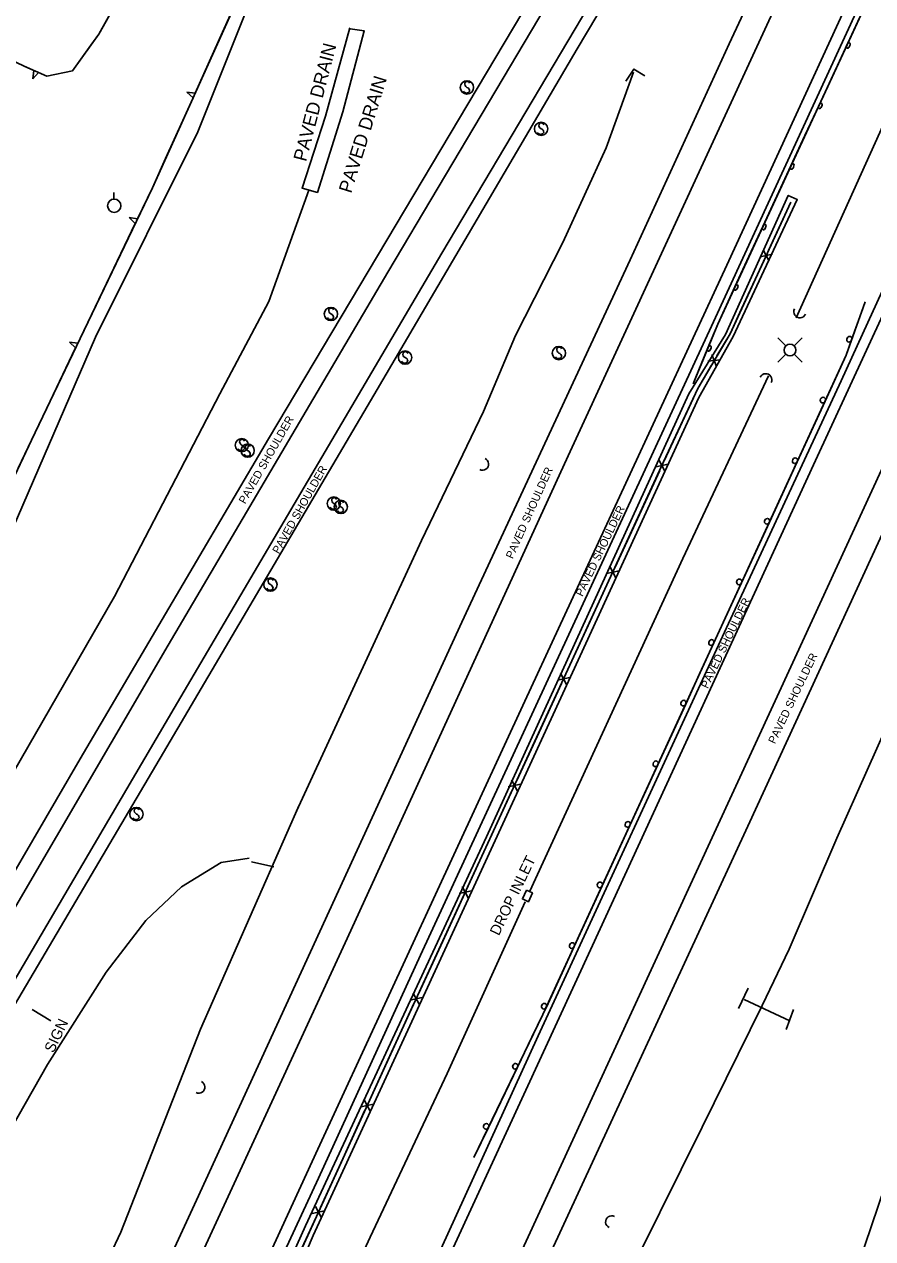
# Model space of a CAD drawing. Extents: x 978516 to 993312, y 1836504 to 1846212.
# Drawn here: x 981689.2 to 982007, y 1842943.3 to 1843398.4 of the extents above; entities that cross this region are included whole.
import ezdxf

# ---------------------------------------------------------------- set-up
doc = ezdxf.new("R2010")
doc.units = 0
for name, color, linetype in [('S_CROSS_DRAIN', 7, 'Continuous'), ('S_DROP_INLET', 7, 'Continuous'), ('S_DROP_INLET_ANNOT', 7, 'Continuous'), ('S_EDGE_PAVEMENT', 7, 'Continuous'), ('S_FENCE', 7, 'Continuous'), ('S_GUARDRAIL', 7, 'Continuous'), ('S_HEADWALL', 7, 'Continuous'), ('S_MISC_STRUCTURES', 7, 'Continuous'), ('S_SHOULDER', 7, 'Continuous'), ('S_SHOULDER_ANNOT', 7, 'Continuous'), ('S_SIDE_DRAIN', 7, 'Continuous'), ('S_SIDE_DRAIN_ANNOT', 7, 'Continuous'), ('S_SIGN', 7, 'Continuous'), ('S_SIGN_ANNOT', 7, 'Continuous'), ('S_STREAM', 7, 'Continuous'), ('S_TRAILS', 7, 'Continuous'), ('S_TREE', 7, 'Continuous'), ('S_UTILITY_POLE', 7, 'Continuous')]:
    doc.layers.add(name, color=color, linetype=linetype)

msp = doc.modelspace()

# ---------------------------------------------------------------- linework, layer by layer
at = {"layer": 'S_CROSS_DRAIN'}
for centre, start, end in [((981979.7, 1843290.68), 153.9932, 334.3223), ((981966.89, 1843265.14), 333.0286, 153.3578), ((981860.81, 1843233.55), 243.9932, 64.3223), ((981754.54, 1843000.07), 243.9932, 64.3223), ((981909.24, 1842949.54), 63.9932, 244.3223)]:
    msp.add_arc(centre, 2.3, start, end, dxfattribs=at)
at = {"layer": 'S_DROP_INLET'}
msp.add_lwpolyline([(981877.3, 1843073.82), (981875.77, 1843070.61), (981877.99, 1843069.55), (981879.53, 1843072.82), (981877.24, 1843073.92)], dxfattribs=at)
at = {"layer": 'S_EDGE_PAVEMENT'}
for points in [[(981545.48, 1842840.54), (981594.83, 1842916.9), (981606.14, 1842933.63), (981624.73, 1842964.36), (981679.78, 1843057.43), (981743.14, 1843165.74), (981825.37, 1843305.52), (981900.71, 1843432.47), (981943.19, 1843504.28), (981976.52, 1843560.47)], [(981988.52, 1843553.82), (981924.19, 1843445.19), (981845.55, 1843312.63), (981745.28, 1843142.12), (981686.64, 1843042.02), (981635.51, 1842955.23), (981602.62, 1842899.17)], [(982046.43, 1843512.73), (982020.19, 1843455.64), (981952.29, 1843308.15), (981876.66, 1843144.67), (981799.12, 1842976.8), (981735.97, 1842839.3)], [(981789.25, 1842808.86), (981838.12, 1842914.35), (981901.96, 1843053.16), (981984.85, 1843233.32), (982064.19, 1843405.17), (982101.67, 1843487.19)], [(981691.52, 1842798.76), (981749.14, 1842923.61), (981810.07, 1843055.75), (981892.92, 1843236.68), (981965.86, 1843394.8), (982005.62, 1843481.17)], [(982119.03, 1843466.37), (982096.74, 1843418.67), (982029, 1843272.11), (981977.78, 1843160.81), (981902.68, 1842997.65), (981844.43, 1842871.29), (981807.01, 1842789.3)]]:
    msp.add_lwpolyline(points, dxfattribs=at)
at = {"layer": 'S_FENCE'}
for p, q in [((981969.44, 1843312.23), (981964.79, 1843311.25)), ((981966, 1843313.85), (981968.24, 1843309.62)), ((981949.97, 1843272.59), (981945.26, 1843272.12)), ((981946.72, 1843274.59), (981948.52, 1843270.13)), ((981926.92, 1843235.12), (981929.17, 1843230.9)), ((981930.37, 1843233.51), (981925.72, 1843232.52)), ((981911.95, 1843193.55), (981907.3, 1843192.56)), ((981908.5, 1843195.17), (981910.75, 1843190.95)), ((981893.53, 1843153.59), (981888.88, 1843152.6)), ((981890.08, 1843155.21), (981892.33, 1843150.99)), ((981875.11, 1843113.63), (981870.46, 1843112.64)), ((981871.66, 1843115.25), (981873.91, 1843111.03)), ((981853.24, 1843075.29), (981855.49, 1843071.07)), ((981856.69, 1843073.67), (981852.04, 1843072.68)), ((981838.28, 1843033.71), (981833.63, 1843032.72)), ((981834.83, 1843035.33), (981837.08, 1843031.11)), ((981819.95, 1842993.72), (981815.3, 1842992.71)), ((981816.49, 1842995.32), (981818.76, 1842991.11)), ((981801.67, 1842953.7), (981797.02, 1842952.68)), ((981798.21, 1842955.29), (981800.48, 1842951.09))]:
    msp.add_line(p, q, dxfattribs=at)
for points in [[(981976.36, 1843331.7), (981953.53, 1843282.4), (981941.43, 1843261.84), (981928.66, 1843234.35), (981829.82, 1843019.91), (981787.4, 1842927.02), (981725.99, 1842788.22)], [(981976.36, 1843331.7), (981967.96, 1843313.55)], [(981966.28, 1843309.92), (981957.87, 1843291.78)], [(981957.87, 1843291.78), (981953.53, 1843282.4), (981948.63, 1843274.08)], [(981946.6, 1843270.63), (981941.43, 1843261.84), (981937.3, 1843252.97)], [(981937.3, 1843252.97), (981928.88, 1843234.83)], [(981927.2, 1843231.2), (981918.83, 1843213.03)], [(981918.83, 1843213.03), (981910.46, 1843194.87)], [(981908.79, 1843191.24), (981900.41, 1843173.08)], [(981900.41, 1843173.08), (981892.04, 1843154.91)], [(981890.37, 1843151.28), (981882, 1843133.12)], [(981882, 1843133.12), (981873.62, 1843114.95)], [(981871.95, 1843111.32), (981863.58, 1843093.16)], [(981863.58, 1843093.16), (981855.21, 1843074.99)], [(981853.53, 1843071.36), (981845.16, 1843053.2)], [(981845.16, 1843053.2), (981836.79, 1843035.04)], [(981835.11, 1843031.4), (981829.82, 1843019.91), (981826.77, 1843013.23)], [(981826.77, 1843013.23), (981818.46, 1842995.04)], [(981816.8, 1842991.4), (981808.49, 1842973.2)], [(981808.49, 1842973.2), (981800.18, 1842955.01)], [(981798.52, 1842951.37), (981790.21, 1842933.18)]]:
    msp.add_lwpolyline(points, dxfattribs=at)
at = {"layer": 'S_GUARDRAIL'}
for points in [[(982087.36, 1843583.1), (982082.81, 1843573.61), (982024.65, 1843449.71), (981948.94, 1843286.05), (981939.76, 1843263.65)], [(982002.6, 1843402.05), (981997.35, 1843390.7)], [(981997.35, 1843390.7), (981986.86, 1843368.01)], [(981986.86, 1843368.01), (981981.61, 1843356.67)], [(981981.61, 1843356.67), (981976.36, 1843345.33)], [(981976.36, 1843345.33), (981965.86, 1843322.64)], [(981965.86, 1843322.64), (981960.62, 1843311.29)], [(981960.62, 1843311.29), (981955.37, 1843299.95)], [(981955.37, 1843299.95), (981948.94, 1843286.05), (981945.27, 1843277.09)], [(981857.6, 1842973.72), (981883.47, 1843027.27), (981997.07, 1843274.39), (982004.19, 1843294.39)], [(982003.27, 1843291.81), (982004.19, 1843294.39)], [(981999.09, 1843280.06), (982003.27, 1843291.81)], [(981989.15, 1843257.16), (981997.07, 1843274.39), (981999.09, 1843280.06)], [(981945.27, 1843277.09), (981940.53, 1843265.52)], [(981940.53, 1843265.52), (981939.76, 1843263.65)], [(981983.93, 1843245.8), (981989.15, 1843257.16)], [(981978.71, 1843234.45), (981983.93, 1843245.8)], [(981968.27, 1843211.73), (981978.71, 1843234.45)], [(981963.05, 1843200.38), (981968.27, 1843211.73)], [(981957.82, 1843189.02), (981963.05, 1843200.38)], [(981947.38, 1843166.31), (981957.82, 1843189.02)], [(981942.16, 1843154.95), (981947.38, 1843166.31)], [(981936.94, 1843143.59), (981942.16, 1843154.95)], [(981926.5, 1843120.88), (981936.94, 1843143.59)], [(981921.28, 1843109.52), (981926.5, 1843120.88)], [(981916.06, 1843098.16), (981921.28, 1843109.52)], [(981905.62, 1843075.45), (981916.06, 1843098.16)], [(981900.39, 1843064.09), (981905.62, 1843075.45)], [(981895.17, 1843052.73), (981900.39, 1843064.09)], [(981884.73, 1843030.02), (981895.17, 1843052.73)], [(981879.35, 1843018.74), (981883.47, 1843027.27), (981884.73, 1843030.02)], [(981873.91, 1843007.49), (981879.35, 1843018.74)], [(981863.04, 1842984.98), (981873.91, 1843007.49)], [(981857.6, 1842973.72), (981863.04, 1842984.98)]]:
    msp.add_lwpolyline(points, dxfattribs=at)
for centre, major_axis, ratio in [((981997.84, 1843390.45), (0.45, 1), 0.498865), ((981987.35, 1843367.77), (0.45, 1), 0.498865), ((981976.85, 1843345.08), (0.45, 1), 0.498865), ((981966.35, 1843322.39), (0.45, 1), 0.498865), ((981955.86, 1843299.7), (0.45, 1), 0.498865), ((981998.2, 1843280.33), (-0.488, -0.986), 0.845733), ((981945.78, 1843276.9), (0.43, 1.01), 0.499215), ((981988.3, 1843257.54), (-0.485, -0.987), 0.845763), ((981977.86, 1843234.83), (-0.485, -0.987), 0.845763), ((981967.42, 1843212.11), (-0.485, -0.987), 0.845763), ((981956.97, 1843189.4), (-0.485, -0.987), 0.845763), ((981946.53, 1843166.69), (-0.485, -0.987), 0.845763), ((981936.09, 1843143.97), (-0.485, -0.987), 0.845763), ((981925.65, 1843121.26), (-0.485, -0.987), 0.845763), ((981915.21, 1843098.54), (-0.485, -0.987), 0.845763), ((981904.77, 1843075.83), (-0.485, -0.987), 0.845763), ((981894.32, 1843053.11), (-0.485, -0.987), 0.845763), ((981883.88, 1843030.4), (-0.485, -0.987), 0.845763), ((981873.07, 1843007.88), (-0.503, -0.978), 0.845636), ((981862.19, 1842985.37), (-0.503, -0.978), 0.845636)]:
    msp.add_ellipse(centre, major_axis=major_axis, ratio=ratio, dxfattribs=at)
at = {"layer": 'S_HEADWALL'}
for points in [[(981921.58, 1843378.99), (981917.56, 1843381.56), (981914.55, 1843377.03)], [(981960.3, 1843037.12), (981956.69, 1843029.59)], [(981974.59, 1843021.7), (981977.26, 1843029.14)]]:
    msp.add_lwpolyline(points, dxfattribs=at)
at = {"layer": 'S_MISC_STRUCTURES'}
msp.add_lwpolyline([(981758.16, 1842855.22), (981769.7, 1842879.28), (981797.37, 1842944.5), (981839.44, 1843035.75), (981897.42, 1843161.73), (981941.83, 1843258.45), (981954.76, 1843281.38), (981978.69, 1843332.66), (981975.37, 1843334.26), (981951.81, 1843282.14), (981938.09, 1843259.87), (981862.35, 1843093.85), (981794.52, 1842948.07), (981784.19, 1842924.99), (981766.14, 1842880.54), (981760.86, 1842869.53)], dxfattribs=at)
at = {"layer": 'S_SHOULDER'}
for points in [[(981966.9, 1843557.79), (981899.61, 1843443.02), (981780.61, 1843243.04), (981710.13, 1843123.14), (981639.11, 1843001.22), (981613.46, 1842958.13), (981583.23, 1842910.42)], [(981607.39, 1842897.85), (981658.24, 1842984.78), (981741.32, 1843125.53), (981820.11, 1843259.39), (981896.33, 1843389.2), (981991.91, 1843549.81)], [(981719.94, 1842772.32), (981757.19, 1842850.86), (981762.83, 1842881.77), (981760.47, 1842881.88), (981799.36, 1842965.97), (981837.6, 1843049.54), (981906.21, 1843198.01), (981947.39, 1843286.92), (982066.73, 1843546.13)], [(981999.81, 1843490.91), (981953.15, 1843391.02), (981916.18, 1843310.13), (981853.12, 1843174.31), (981753.64, 1842957.68), (981723.69, 1842892.74), (981694.78, 1842830.18), (981661.51, 1842757.48)], [(982097.08, 1843486.24), (982039.8, 1843362.56), (981995.19, 1843264.75), (981952.2, 1843172.24), (981881.72, 1843019.31), (981832.85, 1842912.29), (981784.9, 1842808.77)], [(982180.73, 1843461.94), (982147.57, 1843365.49), (982120.53, 1843284.55), (982077.03, 1843155.6), (982029.21, 1843015.14), (981988.83, 1842895.7)], [(981819.67, 1842793.77), (981885.9, 1842937.09), (981960.15, 1843097.91), (982018.44, 1843224.46), (982076.14, 1843348.88), (982122.38, 1843451.81)]]:
    msp.add_lwpolyline(points, dxfattribs=at)
at = {"layer": 'S_SIDE_DRAIN'}
msp.add_lwpolyline([(981811.11, 1843397.07), (981801.98, 1843363.99), (981793.23, 1843336.95), (981798.96, 1843335.36), (981808.46, 1843365.59), (981816.54, 1843395.96), (981811.27, 1843396.72)], dxfattribs=at)
at = {"layer": 'S_SIGN'}
msp.add_lwpolyline([(981699.19, 1843024.95), (981692.18, 1843029.18)], dxfattribs=at)
for centre in [(981855, 1843374.72), (981882.76, 1843359.2), (981804.05, 1843289.8), (981831.82, 1843273.47), (981889.43, 1843275.16), (981770.67, 1843240.63), (981772.86, 1843238.6), (981805.14, 1843218.76), (981807.76, 1843217.5), (981781.37, 1843188.38), (981731.19, 1843102.39)]:
    msp.add_circle(centre, 2.49, dxfattribs=at)
for centre, radius, start, end in [((981855.69, 1843376.04), 1.5, 167.1196, 241.9813), ((981855.08, 1843375.98), 0.95, 16.5258, 156.8957), ((981854.85, 1843373.89), 1.28, 204.641, 335.359), ((981854.59, 1843373.37), 1.4, 358.6529, 73.7063), ((981882.83, 1843360.47), 0.95, 16.5258, 156.8957), ((981882.61, 1843358.38), 1.28, 204.641, 335.359), ((981883.45, 1843360.53), 1.5, 167.1196, 241.9813), ((981882.35, 1843357.86), 1.4, 358.6529, 73.7063), ((981803.9, 1843288.98), 1.28, 204.641, 335.359), ((981804.74, 1843291.13), 1.5, 167.1196, 241.9813), ((981804.13, 1843291.07), 0.95, 16.5258, 156.8957), ((981803.64, 1843288.46), 1.4, 358.6529, 73.7063), ((981832.51, 1843274.8), 1.5, 167.1196, 241.9813), ((981831.9, 1843274.74), 0.95, 16.5258, 156.8957), ((981890.12, 1843276.49), 1.5, 167.1196, 241.9813), ((981889.51, 1843276.43), 0.95, 16.5258, 156.8957), ((981889.02, 1843273.82), 1.4, 358.6529, 73.7063), ((981831.67, 1843272.65), 1.28, 204.641, 335.359), ((981831.41, 1843272.13), 1.4, 358.6529, 73.7063), ((981889.28, 1843274.34), 1.28, 204.641, 335.359), ((981770.74, 1843241.9), 0.95, 16.5258, 156.8957), ((981770.51, 1843239.81), 1.28, 204.641, 335.359), ((981771.35, 1843241.96), 1.5, 167.1196, 241.9813), ((981770.25, 1843239.29), 1.4, 358.6529, 73.7063), ((981773.55, 1843239.92), 1.5, 167.1196, 241.9813), ((981772.94, 1843239.86), 0.95, 16.5258, 156.8957), ((981772.45, 1843237.25), 1.4, 358.6529, 73.7063), ((981772.71, 1843237.77), 1.28, 204.641, 335.359), ((981805.82, 1843220.09), 1.5, 167.1196, 241.9813), ((981805.21, 1843220.03), 0.95, 16.5258, 156.8957), ((981804.98, 1843217.94), 1.28, 204.641, 335.359), ((981804.72, 1843217.42), 1.4, 358.6529, 73.7063), ((981807.61, 1843216.68), 1.28, 204.641, 335.359), ((981808.44, 1843218.83), 1.5, 167.1196, 241.9813), ((981807.83, 1843218.77), 0.95, 16.5258, 156.8957), ((981807.35, 1843216.16), 1.4, 358.6529, 73.7063), ((981782.06, 1843189.71), 1.5, 167.1196, 241.9813), ((981781.45, 1843189.65), 0.95, 16.5258, 156.8957), ((981780.96, 1843187.04), 1.4, 358.6529, 73.7063), ((981781.22, 1843187.56), 1.28, 204.641, 335.359), ((981731.88, 1843103.72), 1.5, 167.1196, 241.9813), ((981731.27, 1843103.66), 0.95, 16.5258, 156.8957), ((981730.78, 1843101.05), 1.4, 358.6529, 73.7063), ((981731.04, 1843101.57), 1.28, 204.641, 335.359)]:
    msp.add_arc(centre, radius, start, end, dxfattribs=at)
at = {"layer": 'S_STREAM'}
for points in [[(981978.35, 1843288.32), (982014.3, 1843368), (982033.99, 1843411.83)], [(981917.35, 1843380.48), (981907.14, 1843352.07), (981890.96, 1843316.6), (981873.22, 1843281.73), (981861.21, 1843253.29), (981837.97, 1843204.86), (981791.21, 1843103.54)], [(982130.67, 1843375.87), (982124.43, 1843373.38), (982091.6, 1843305.09), (982064.06, 1843250.26), (982027.58, 1843169.81), (981993.6, 1843093.36), (981975.63, 1843051.79), (981965.53, 1843030.7), (981943.1, 1842985.12), (981911.5, 1842921.4), (981867.59, 1842836.56), (981838.87, 1842783.35)], [(981552.74, 1842897.71), (981599.88, 1842973.31), (981685.22, 1843118.3), (981722.94, 1843183.9), (981762.49, 1843259.91), (981780.74, 1843294.54), (981795.73, 1843336.24)], [(981878.59, 1843073.45), (981935.85, 1843198.23), (981967.92, 1843266.59)], [(981657.21, 1842806.07), (981688.31, 1842867.04), (981725.3, 1842945.72), (981755.24, 1843021.83), (981792.1, 1843105.71)], [(981565.85, 1842777.95), (981636.06, 1842900.92), (981667.36, 1842955.08), (981697.92, 1843008.49), (981719.82, 1843043.2), (981734.73, 1843062.5), (981748.12, 1843075.16), (981762.92, 1843084.24), (981773.36, 1843085.89)], [(981774.3, 1843084.53), (981782.64, 1843082.6)], [(981755.72, 1842807.22), (981818.73, 1842943.87), (981847.59, 1843005.12), (981876.79, 1843069.57)], [(981958.79, 1843032.85), (981975.91, 1843024.9)]]:
    msp.add_lwpolyline(points, dxfattribs=at)
at = {"layer": 'S_TRAILS'}
msp.add_lwpolyline([(981896.17, 1843674.76), (981875.66, 1843622.83), (981848.09, 1843561.02), (981825.69, 1843517.28), (981813.48, 1843491.81), (981796.39, 1843459.31), (981777.43, 1843416.32), (981754.21, 1843358.04), (981715.88, 1843281.16), (981681.06, 1843200.57), (981657.31, 1843142.13), (981626.44, 1843080.32), (981598.91, 1843029.49), (981571.02, 1842980.89), (981523.66, 1842903.06)], dxfattribs=at)
at = {"layer": 'S_TREE'}
for p, q in [((981692.7, 1843381.09), (981692.37, 1843377.96)), ((981692.37, 1843377.96), (981694.5, 1843380.31)), ((981753.21, 1843372.61), (981750.09, 1843372.99)), ((981750.09, 1843372.99), (981752.4, 1843370.82)), ((981731.62, 1843325.46), (981728.52, 1843325.92)), ((981728.52, 1843325.92), (981730.78, 1843323.7)), ((981709.26, 1843278.86), (981706.15, 1843279.3)), ((981706.15, 1843279.3), (981708.41, 1843277.08))]:
    msp.add_line(p, q, dxfattribs=at)
for points in [[(981780.65, 1843433.53), (981737.2, 1843337.08), (981710.12, 1843280.65), (981691.84, 1843242.53), (981658.1, 1843171.03), (981630.4, 1843113.29), (981610.27, 1843071.25), (981593.52, 1843036.17), (981562.15, 1842980.99), (981523.54, 1842914.67)], [(981636.87, 1843408), (981657.47, 1843397.83), (981678.04, 1843387.96), (981689.16, 1843382.63), (981697.67, 1843378.94), (981707.27, 1843380.93), (981717.05, 1843394.68), (981733.82, 1843424.52)], [(981773.72, 1843418.16), (981763.46, 1843395.38)], [(981714.07, 1843390.49), (981717.05, 1843394.68), (981726.78, 1843412)], [(981763.46, 1843395.38), (981753.21, 1843372.61)], [(981670.1, 1843391.77), (981678.04, 1843387.96), (981689.16, 1843382.63), (981692.7, 1843381.09)], [(981694.5, 1843380.31), (981697.67, 1843378.94), (981707.27, 1843380.93), (981714.07, 1843390.49)], [(981752.4, 1843370.82), (981742.14, 1843348.05)], [(981742.14, 1843348.05), (981737.2, 1843337.08), (981731.62, 1843325.46)], [(981730.78, 1843323.7), (981720.02, 1843301.28)], [(981720.02, 1843301.28), (981710.12, 1843280.65), (981709.26, 1843278.86)], [(981708.41, 1843277.08), (981697.6, 1843254.55)], [(981697.6, 1843254.55), (981691.84, 1843242.53), (981686.86, 1843231.99)]]:
    msp.add_lwpolyline(points, dxfattribs=at)
at = {"layer": 'S_UTILITY_POLE'}
for p, q in [((981722.72, 1843332.89), (981722.72, 1843335.37)), ((981974.39, 1843277.86), (981971.41, 1843280.85)), ((981977.57, 1843277.86), (981980.55, 1843280.85)), ((981974.39, 1843274.69), (981971.41, 1843271.7)), ((981977.57, 1843274.69), (981980.55, 1843271.7))]:
    msp.add_line(p, q, dxfattribs=at)
for centre, radius in [((981722.87, 1843330.37), 2.5), ((981975.99, 1843276.28), 2.21)]:
    msp.add_circle(centre, radius, dxfattribs=at)

# ---------------------------------------------------------------- texts
at = {"layer": 'S_DROP_INLET_ANNOT'}
msp.add_text('DROP INLET', height=4, rotation=64.3687, dxfattribs=at).set_placement((981866.96, 1843056.57))
at = {"layer": 'S_SHOULDER_ANNOT'}
for rotation, p in [(60.2716, (981771.92, 1843218.38)), (60.5083, (981784.52, 1843199.67)), (65.9093, (981872.14, 1843197.81)), (64.3687, (981898.24, 1843183.7)), (64.3687, (981945.18, 1843149.19)), (64.3687, (981970.38, 1843128.46))]:
    msp.add_text('PAVED SHOULDER', height=3.0003, rotation=rotation, dxfattribs=at).set_placement(p)
at = {"layer": 'S_SIDE_DRAIN_ANNOT'}
for rotation, p in [(75.4384, (981794.74, 1843346.65)), (72.7415, (981811.62, 1843334.78))]:
    msp.add_text('PAVED DRAIN', height=5.0005, rotation=rotation, dxfattribs=at).set_placement(p)
at = {"layer": 'S_SIGN_ANNOT'}
msp.add_text('SIGN', height=4, rotation=64.3687, dxfattribs=at).set_placement((981700.11, 1843012.62))

doc.saveas('drawing.dxf')
